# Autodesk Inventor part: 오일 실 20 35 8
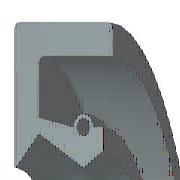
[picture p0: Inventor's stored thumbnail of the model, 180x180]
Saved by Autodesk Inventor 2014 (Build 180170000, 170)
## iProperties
IsCustomPart: 0
Created: 2018-09
Part Number: 오일 실 20 35 8
Material: 고무
Description: 오일-실
Document SubType Name: Modeling
Standard: KS B 2804
Standards Organization: KS
Language: ko-KR
Size Designation: D - 20 35 8
Categories: <MemberInstance><Categories><Category DisplayName="샤프트 부품" InternalName="7f7aeb1f-a693-4053-b835-cee3144e0d98" Mnemonic="SHFT"><Category DisplayName="실링" Intern
Density: 0.93 g/cm^3
Mass: 2.54606 g
Surface Area: 35.9421 cm^2
Volume: 2.7377 cm^3
Appearance: 고무 - 검은색 - 버전 1.1
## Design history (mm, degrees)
revolve "본체" stored, may be unused: angle "d17" = 90 deg
revolve "스프링1" stored, may be unused: angle "d18" = 90 deg
body "Solid1"
sketch "스케치1"
  geometry: L1 (0, 17.5)-(8, 17.5); L2 (8, 15.75)-(1.75, 15.75); L3 (1.75, 11.75)-(4.9, 10); L4 (4.9, 10)-(0, 10); L5 (0, 0)-(9.586, 0) reference; L6 (4.9, 10)-(6.3, 10.875); L7 (0, 18)-(0, -3) reference; L8 (-1.941, 0)-(11.507, 0) reference; L9 (4.2, 12.1)-(1.75, 12.71); L10 (1.75, 12.71)-(1.75, 15.75); L11 (0, 17.5)-(0, 10.088); L12 (4.9, 10)-(0, 10); L13 (1.75, 11.75)-(0.152, 10.028); L14 (8, 17.5)-(8, 15.75); L15 (5.6, 12.1)-(6.3, 12.1); L16 (6.3, 12.1)-(6.3, 10.875); C1 r 0.455 at (4.9, 12.1); A1 r 0.7 centre (4.9, 12.1) between (5.6, 12.1) and (4.2, 12.1); A2 r 0.088 centre (0.088, 10.088) between (0, 10.088) and (0.152, 10.028); 1 further point
  constraints: 28 end point, 5 horizontal alignment, 5 point on line, 4 point on circle, 4 vertical alignment, 3 centre point, 3 tangent, 2 collinear, 2 horizontal, 2 perpendicular, 1 coincident, 1 parallel
  dimensions: "d0" = 35 diameter of L1 L5 (= SD2); "d1" = 1.75 distance of L1.end L2.start (= SD); "d2" = 0.91 diameter of C1 (= SPDI); "d3" = 1.4 diameter of A1 (= SPDA); "d4" = 20 diameter of L3.end L5 (= NND); "d5" = 23.5 diameter of L3.start L5 (= TKDM); "d7" = 25.42 diameter of L9.end L5 (= TKDM + 0.24 x SWDT); "d8" = 1.75 distance between parallel lines of L11 L10 (= SD); "d9" = 4.9 distance from line of L11 C1.centre (= SPDST); "d10" = 24.2 diameter of C1.centre L5 (= HLDM); "d11" = 0.0875 radius of A2 (= 0.25 x LAB); "d12" = 6.3 distance between parallel lines of L11 L16 (= SDI); "d13" = 21.75 diameter of L6.end L5 (= ABDM); "d14" = 8 distance from line of L11 L1.end (= SWDT)
fillet "모깎기1" dims "d6" = 0.3 (= RR)
other parameters: "SD2" = 35 [user parameter; used in 1 equation term], "SWDT" = 8 [user parameter; used in 2 equation terms], "RR" = 0.3 [user parameter; used in 1 equation term], "SD" = 1.75 [user parameter; used in 2 equation terms], "NND" = 20 [user parameter; used in 1 equation term], "SPDA" = 1.4 [user parameter; used in 1 equation term], "SPDI" = 0.91 [user parameter; used in 1 equation term], "TKDM" = 23.5 [user parameter; used in 2 equation terms], "HLDM" = 24.2 [user parameter; used in 1 equation term], "ABDM" = 21.75 [user parameter; used in 1 equation term], "SDI" = 6.3 [user parameter; used in 1 equation term], "SPDST" = 4.9 [user parameter; used in 1 equation term], "LAB" = 0.35 [user parameter; used in 1 equation term], "d15" = 0, "d16" = 0, "d19" = 0
